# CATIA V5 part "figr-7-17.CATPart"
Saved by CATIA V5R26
Part number: Part2
Bounding box of the stored display mesh (mm): x -50 to 50, y -65 to 65, z 0 to 28
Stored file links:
  D:\_Deepak\CATIA\CATIA V5-6R2016_Deepak\Resources\Part files\Partfiles\c07_catia_v5_6r2016_prt\figr-7-17.CATPart
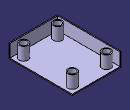
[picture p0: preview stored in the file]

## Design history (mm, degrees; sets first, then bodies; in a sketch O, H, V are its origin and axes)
Body1 (main body)
  Sketch1 on xy-plane, origin (0, 0, 0), H (1, 0, 0), V (0, 1, 0)
    line L1 (-50, 65) -> (50, 65)
    line L2 (50, 65) -> (50, -65)
    line L3 (50, -65) -> (-50, -65)
    line L4 (-50, -65) -> (-50, 65)
    axis line L5 (50, -65) -> (-50, 65)
    length L3 = 100
    length L2 = 130
    horizontal: L1 H, L3 H
    vertical: L2 V, L4 V
    midpoint: O L5
  Pad1: profile Sketch1, direction (0, 0, 1), length 28
  Sketch2 on face of Pad1, origin (25.9302, -33.7092, 28), H (1, 0, 0), V (0, 1, 0)
    point P1 (9.0698, -16.2908)
    reference projected line E1 (-75.9302, -31.2908) -> (24.0698, -31.2908) from edge [face of Pad1 | face of Pad1]
    reference projected line E2 (24.0698, -31.2908) -> (24.0698, 98.7092) from edge [face of Pad1 | face of Pad1]
    distance P1 E1 = 15
    distance P1 E2 = 15
  Hole1: placed by Sketch2, at (35, -50, 28) direction (0, 0, -1), diameter 14, through (limit type 3)
  RectPattern1: of Hole1, direction 1 instances 2, spacing 100, along edge [face of Pad1 | face of Pad1], direction 2 instances 2, spacing 70, along edge [face of Pad1 | face of Pad1]
  Shell1: ExtOffset 0, Face (face of Pad1; face of Pad1; face of Pad1), IntOffset 2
